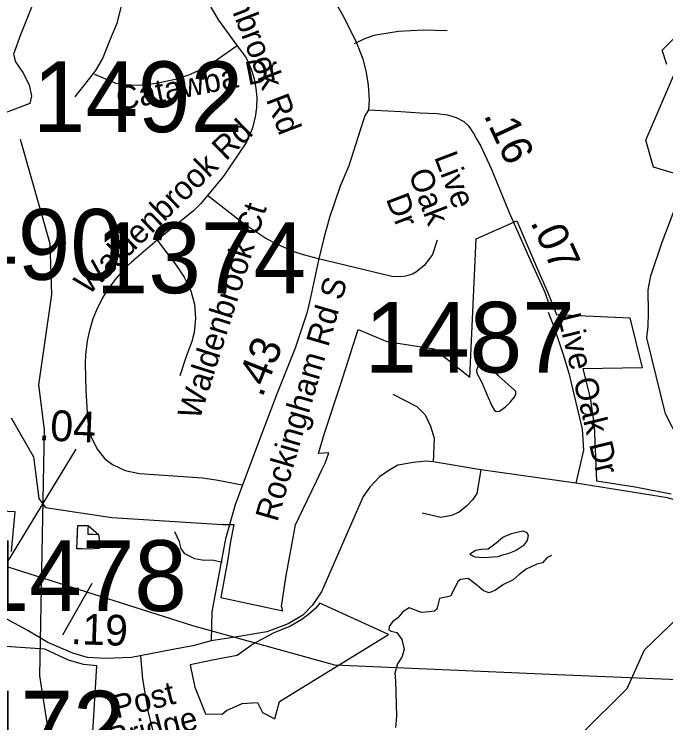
# Model space of a CAD drawing. Extents: x 1662474 to 1856135, y 779280 to 917889.
# Drawn here: x 1735258 to 1737912, y 817764 to 820649 of the extents above; entities that cross this region are included whole.
import ezdxf

# ---------------------------------------------------------------- set-up
doc = ezdxf.new("R2010")
doc.units = 0
for name, color, linetype in [('Cogo Default Point CELL', 7, 'Continuous'), ('Exist Boundary Political City Limit New', 7, 'Continuous'), ('Exist Boundary Political City Limit New Hole', 7, 'Continuous'), ('Exist Hydrographic Creek Single Shore', 7, 'Continuous'), ('Exist Hydrographic Misc Water Feature', 7, 'Continuous'), ('Exist Hydrographic Pond Under 1500 Sq Ft', 7, 'Continuous'), ('Exist Road Non-System Type 51', 7, 'Continuous'), ('Exist Road Non-System Type 51 Label', 7, 'Continuous'), ('Exist Road Secondary Mileage Tenths English Label', 7, 'Continuous'), ('Exist Road Secondary Type 51 Attributed', 7, 'Continuous'), ('Exist Road Secondary Type 51 Label', 7, 'Continuous'), ('Exist Utilities Electrical Transmission Line', 7, 'Continuous'), ('Map Preparation Boundary City Limit Buffer Line', 7, 'Continuous'), ('Prop DGN Element Guardrail', 7, 'Continuous')]:
    doc.layers.add(name, color=color, linetype=linetype)

msp = doc.modelspace()

# ---------------------------------------------------------------- linework, layer by layer
at = {"layer": 'Exist Boundary Political City Limit New'}
for points in [[(1737915.6, 820444.8), (1737896.8, 820502.2), (1737962.2, 820567.4)], [(1738049.1, 818752), (1737910.5, 819022.8), (1737834.9, 819331), (1737840.5, 819379.6), (1737841.6, 819433.6), (1737839.6, 819526.6), (1737850.8, 819583.7), (1737896.6, 819720.4), (1737997.5, 819985.3), (1737862, 820026.4), (1737831, 820135.9), (1737947.4, 820407.4)], [(1735245.1, 819006.1), (1735336, 818847.1), (1735358.5, 818677.1), (1735384.9, 818640.8), (1735655.2, 818599.9), (1736105.6, 818571.8), (1736153, 818571.2), (1736139.2, 818502.4), (1736126.9, 818421.8), (1736099.4, 818274.9), (1736352.2, 818220.5), (1736347, 818237.8), (1736364.5, 818355.5), (1736403.2, 818570.9), (1736433.1, 818632.6), (1736489, 818748.3), (1736511.2, 818794.4), (1736524.5, 818821.8), (1736539.2, 818863.3), (1736498, 818860.2), (1736521.8, 818943.9), (1736587.1, 819140.1), (1736659.2, 819365.4), (1736775.4, 819316), (1736968.6, 819287.2), (1737114.1, 819171.2), (1737139.5, 819734.6), (1737304.9, 819807.4), (1737385.9, 819621.1), (1737433, 819512.2), (1737467.2, 819425.9), (1737766.2, 819412.8), (1737815.8, 819209), (1737573.8, 819205.9), (1737604.4, 819087.4), (1737620.5, 818974.2), (1737630, 818749.4), (1737787.1, 818725.4), (1737933.5, 818696.2)], [(1735247, 818461.5), (1735262.1, 818622.6), (1735081.5, 818631.2)], [(1738046, 817674.9), (1738138.4, 818307.4), (1738180.8, 818423.3), (1738135.1, 818381.3), (1738071.8, 818298.6), (1737823.9, 818060.2), (1737752.9, 817902.8), (1737570.5, 817721)], [(1735560.4, 817433), (1735594.5, 817996.6), (1735540.2, 818001.2), (1735479.1, 818018.8), (1735382.8, 818064.1), (1735203.4, 818076.8)]]:
    msp.add_lwpolyline(points, dxfattribs=at)
at = {"layer": 'Exist Boundary Political City Limit New Hole'}
msp.add_lwpolyline([(1736487.1, 818231.6), (1736457.2, 818205.4), (1736429.8, 818185.2), (1736380.5, 818157), (1736315.1, 818131), (1736232.2, 818085.8), (1736165.8, 818037.7), (1736064.9, 818018.8), (1735974.2, 818000.2), (1735985.1, 817947.1), (1735992.9, 817909), (1736037.6, 817801.4), (1736104.9, 817799.7), (1736122.9, 817814.8), (1736186, 817843.1), (1736248.9, 817847.3), (1736269.8, 817806.8), (1736319.4, 817780.8), (1736338.9, 817850.5), (1736782.2, 818124.1), (1736503.2, 818251), (1736487.1, 818231.6)], dxfattribs=at)
at = {"layer": 'Exist Hydrographic Creek Single Shore'}
msp.add_lwpolyline([(1737446.2, 818445.3), (1737426.9, 818436.1), (1737410, 818415.4), (1737386.9, 818409.9), (1737343.4, 818389.6), (1737314.2, 818368.6), (1737290.6, 818346.1), (1737251, 818326.9), (1737219, 818303.6), (1737192.5, 818293.9), (1737170.1, 818301.8), (1737141, 818325.6), (1737106.9, 818351.9), (1737076.1, 818347.4), (1737066.2, 818340.8), (1737035.5, 818279.7), (1736989.6, 818270.8), (1736979.6, 818227.4), (1736969.4, 818218.2), (1736948.4, 818215.4), (1736917.1, 818213.8), (1736867.2, 818231.9), (1736841, 818215.9), (1736820.2, 818191.8), (1736799, 818174.7), (1736785.6, 818156.3), (1736783.8, 818143.2), (1736793.2, 818137.9), (1736817.1, 818132.4), (1736836.2, 818102.8), (1736846, 818062.9), (1736836.2, 818031.6), (1736818.5, 818004.4), (1736808.8, 817966), (1736811.1, 817934.8), (1736814.5, 817791.8), (1736810.6, 817745.8)], dxfattribs=at)
at = {"layer": 'Exist Hydrographic Misc Water Feature'}
for points in [[(1735582.6, 816470.9), (1735584.6, 816746.5), (1735511.6, 816961.3), (1735555.7, 817203.3), (1735532.7, 817413.9), (1735402.7, 817695.5), (1735362.8, 817955.7), (1735380.6, 818956.4), (1735357.6, 819140.7), (1735410.7, 819507.3), (1735404.6, 819714.2), (1735283, 820139.1)], [(1735603.5, 818473.4), (1735565.3, 818471.7), (1735533.4, 818472.1), (1735513.3, 818472.3), (1735513.7, 818504.2), (1735516.1, 818548.2), (1735516.3, 818568.2), (1735534.4, 818568.1), (1735558.4, 818567.9), (1735558, 818549.9), (1735558, 818531.9), (1735577.9, 818531.7), (1735601.8, 818531.4), (1735603.7, 818513.4), (1735601.4, 818495.4), (1735603.5, 818473.4)], [(1735603.5, 818473.4), (1735565.3, 818471.7), (1735533.4, 818472.1), (1735513.3, 818472.3), (1735513.7, 818504.2), (1735516.3, 818568.2), (1735534.4, 818568.1), (1735558.4, 818567.9), (1735601.8, 818531.4), (1735603.7, 818513.4), (1735603.5, 818473.4)]]:
    msp.add_lwpolyline(points, dxfattribs=at)
at = {"layer": 'Exist Hydrographic Pond Under 1500 Sq Ft'}
for points in [[(1735429.9, 820932.9), (1735284.1, 820565.7), (1735255, 820487), (1735263.7, 820455), (1735292.9, 820411.2), (1735319.1, 820361.7), (1735327.9, 820315.1), (1735322, 820285.9), (1735036.3, 820178.1), (1735010, 820189.8), (1734986.7, 820303.4), (1734896.3, 820449.1), (1734800.1, 820539.5), (1734709.7, 820583.2), (1734657.2, 820615.3), (1734645.6, 820650.2)], [(1737296.2, 819119), (1737231.6, 819175.1), (1737188.4, 819213.9), (1737170.3, 819223.3), (1737156.5, 819220.7), (1737145.3, 819210.4), (1737141, 819200.1), (1737142.7, 819188), (1737162.6, 819150.1), (1737176.4, 819116.5), (1737188.4, 819088.9), (1737204, 819054.4), (1737212.6, 819038.9), (1737221.2, 819031.1), (1737234.1, 819032.9), (1737259.2, 819050.1), (1737279.8, 819071.6), (1737295.4, 819090.6), (1737301.4, 819103.5), (1737301.4, 819113), (1737296.2, 819119)], [(1737228.3, 818439.7), (1737171.2, 818435.8), (1737134.9, 818438.4), (1737116.7, 818447.5), (1737115.4, 818452.6), (1737136.2, 818466.9), (1737159.6, 818470.8), (1737188.1, 818472.1), (1737220.5, 818496.7), (1737247.8, 818520.1), (1737284.1, 818534.3), (1737311.3, 818542.1), (1737330.8, 818546), (1737346.4, 818539.5), (1737351.6, 818526.6), (1737347.7, 818507.1), (1737330.8, 818485.1), (1737302.3, 818465.6), (1737268.5, 818452.6), (1737246.5, 818446.2), (1737228.3, 818439.7)]]:
    msp.add_lwpolyline(points, dxfattribs=at)
at = {"layer": 'Exist Road Non-System Type 51'}
for p, q in [((1737158.6, 818794.1), (1736964.9, 818827.2)), ((1737545.4, 818740.2), (1737158.6, 818794.1))]:
    msp.add_line(p, q, dxfattribs=at)
for points in [[(1735969.1, 821413.4), (1735970.9, 821250.2), (1735983, 820947.1), (1735986.4, 820911.1), (1735999.5, 820838.7), (1736020.9, 820765.9), (1736060.6, 820675.4), (1736089.9, 820625.2), (1736166.5, 820519.8)], [(1737021.4, 820582), (1736923.4, 820583.5), (1736822.6, 820578.2), (1736722.6, 820561.8), (1736685.1, 820548.1), (1736643.1, 820528.4)], [(1736166.5, 820519.8), (1736070.6, 820453.4), (1736002.4, 820415.6), (1735967.2, 820401.2), (1735913.1, 820383.6), (1735837.1, 820366.8), (1735764.9, 820359.4), (1735704.5, 820361.8), (1735673.6, 820367), (1735585.6, 820404)], [(1736166.5, 820519.8), (1736199.9, 820474.9), (1736209, 820458.1), (1736224.1, 820421.4), (1736235.2, 820385.4), (1736242.6, 820347.9), (1736245.8, 820309.2), (1736244.9, 820269.4), (1736239.6, 820230), (1736227.6, 820182.5), (1736204.5, 820128.4), (1736110, 819989.1), (1736045.8, 819910.6)], [(1736045.8, 819910.6), (1736016.6, 819876.8), (1735988, 819848.9), (1735840.2, 819728.7)], [(1736497.4, 819653.7), (1736436, 819669.9), (1736398.2, 819682.2), (1736330.2, 819711.1), (1736282.5, 819736.1), (1736192.8, 819795.9), (1736045.8, 819910.6)], [(1735840.2, 819728.7), (1735735, 819640), (1735707.1, 819613.5), (1735669.9, 819570.2), (1735636.6, 819525.4), (1735617.9, 819494.9), (1735592.8, 819443.7), (1735578.6, 819408.5), (1735562.5, 819356.2), (1735554.9, 819319.2), (1735547.6, 819262.6), (1735546.8, 819226.9), (1735549.4, 819116.9), (1735556.2, 819005.1), (1735560.6, 818969.4), (1735570.4, 818931.6), (1735595.6, 818878.1), (1735626.9, 818839.5), (1735658.4, 818815.6), (1735710.1, 818792), (1735768.1, 818779.1), (1736024.2, 818761), (1736080.6, 818753.4), (1736186.4, 818733.4)], [(1735840.2, 819728.7), (1735917.6, 819626.9), (1735949.6, 819578.9), (1735976.1, 819526.6), (1735991.9, 819468.6), (1735996.9, 819410.1), (1735991.4, 819353.9), (1735981.4, 819316.4), (1735956.8, 819251), (1735932.1, 819176.2)], [(1736980.9, 819728.7), (1736961.1, 819671.2), (1736950.6, 819655.5), (1736927.1, 819626.4), (1736896.9, 819600.6), (1736879.6, 819591.2), (1736851.5, 819582), (1736831.9, 819579.9), (1736795.9, 819581.8), (1736497.4, 819653.7)], [(1737432.7, 819435.5), (1737457, 819373.4), (1737494.5, 819264.2), (1737517.1, 819187.2), (1737571.9, 818959.9), (1737577.1, 818874.7), (1737545.4, 818740.2)], [(1736800.1, 819102.2), (1736897.6, 819052.6), (1736932.1, 819018.2), (1736954.1, 818971.8), (1736968.9, 818922.7), (1736964.9, 818827.2)], [(1736964.9, 818827.2), (1736935.8, 818829.8), (1736884.4, 818823.5), (1736820.5, 818812.8), (1736787.4, 818794.4), (1736745.8, 818766), (1736706.4, 818723.8), (1736678.8, 818686.2), (1736509.8, 818297.2), (1736471.6, 818242.4), (1736433.4, 818202.8), (1736374.4, 818166.8), (1736286.4, 818135), (1736165.4, 818114.9), (1736059.9, 818097.8)], [(1737158.6, 818794.1), (1737142.6, 818697.2), (1737125.5, 818673.1), (1737100.9, 818647.4), (1737070.1, 818621.7), (1737038.9, 818608), (1736995.6, 818600.7), (1736919.8, 818617.7)], [(1738249.6, 818457.9), (1738006.9, 818643.7), (1737974.4, 818663.4), (1737918.9, 818680.7), (1737545.4, 818740.2)], [(1736104.8, 818416.9), (1736071.1, 818424.6), (1736023.9, 818425.9), (1735993.4, 818432.1), (1735952.9, 818452.4), (1735937.9, 818474.4), (1735930.9, 818501.5), (1735912, 818541.2)], [(1735772, 818036.1), (1735779.9, 817941.4), (1735803.2, 817805.9), (1735825, 817720.9), (1735881.1, 817612.2), (1735989.9, 817422.2), (1736031.4, 817340.9), (1736044.1, 817273.9), (1736065.6, 817035.1), (1736080.1, 816997), (1736138.1, 816930.4)]]:
    msp.add_lwpolyline(points, dxfattribs=at)
at = {"layer": 'Exist Road Secondary Mileage Tenths English Label'}
msp.add_line((1735150.7, 818289.2), (1735510.2, 818877.7), dxfattribs=at)
at = {"layer": 'Exist Road Secondary Type 51 Attributed'}
for points in [[(1736594.9, 821695.7), (1736536.5, 821560.8), (1736502.9, 821480.2), (1736481.1, 821404.7), (1736461.2, 821321.5), (1736451.1, 821264.4), (1736424.3, 821093.3), (1736424.3, 821022.8), (1736429.3, 820979.2), (1736441.1, 820933.9), (1736471, 820862.7), (1736531.5, 820758.6), (1736595.3, 820646.2), (1736649, 820538.8), (1736678.1, 820466.8), (1736691.2, 820412.3), (1736699.9, 820360.1), (1736703.2, 820300.4), (1736701.3, 820259.6)], [(1735304.2, 821558.3), (1735388.6, 821494.4), (1735462.1, 821424.7), (1735541.5, 821329.5), (1735582.5, 821279), (1735620.8, 821213), (1735650.8, 821146.1), (1735668.4, 821086), (1735700.2, 820959), (1735708.3, 820897.5), (1735710.8, 820826.7), (1735704.7, 820755.6), (1735693.6, 820683.3), (1735675.9, 820611.1), (1735646, 820540.7), (1735618.5, 820471.1), (1735589.1, 820419.3), (1735504.3, 820312.7)], [(1736701.3, 820259.6), (1736686.1, 820234.7), (1736667.7, 820177.6), (1736620.4, 820031.8), (1736585.6, 819949.4), (1736541.6, 819821.2), (1736518.6, 819737), (1736497.6, 819647.1), (1736465, 819496), (1736457.4, 819465.4), (1736449.3, 819431.3), (1736402.1, 819289.8), (1736329.1, 819106.2), (1736265.9, 818941.9), (1736194.1, 818751), (1736158, 818651.6), (1736118.3, 818513.2), (1736063.1, 818216.7), (1736059.9, 818097.8)], [(1736701.3, 820259.6), (1736832.7, 820253.1), (1736911.6, 820248.1), (1736980.5, 820244.7), (1737022.4, 820239.7), (1737057.7, 820227.9), (1737089.6, 820212.8), (1737107.1, 820195.8), (1737119.7, 820178.6), (1737130.6, 820161.4), (1737141.5, 820141.5), (1737158.7, 820111.7), (1737200.4, 820021.5), (1737274.3, 819842), (1737358.2, 819652.4), (1737419.4, 819517.3), (1737437.1, 819465.6)], [(1736059.9, 818097.8), (1735986, 818077.5), (1735897.1, 818061.9), (1735735.4, 818030.6), (1735629.6, 818026.1), (1735555.8, 818030.6), (1735496, 818047.9), (1735395.4, 818090.9), (1735311.2, 818140.9), (1735176.7, 818213.3), (1735019.8, 818296.8)]]:
    msp.add_lwpolyline(points, dxfattribs=at)
at = {"layer": 'Exist Road Secondary Type 51 Label'}
msp.add_lwpolyline([(1735574.6, 818330.9), (1735454.6, 818121.1)], dxfattribs=at)
msp.add_lwpolyline([(1735574.6, 818330.9), (1735454.6, 818121.1)], dxfattribs=at)
at = {"layer": 'Exist Utilities Electrical Transmission Line'}
msp.add_lwpolyline([(1740410.3, 818536), (1739647.3, 818606.7), (1738818.7, 818695.7), (1738408.3, 818240), (1738124, 817932.3), (1737470.7, 817959.1), (1736563.3, 817999.5), (1735985.6, 818159.3), (1735318.6, 818370.5), (1734562, 818610.7), (1734385.1, 818673.4), (1733771.7, 818709.9), (1733130.2, 818752.5), (1733004.3, 818758.3)], dxfattribs=at)
at = {"layer": 'Map Preparation Boundary City Limit Buffer Line'}
for points in [[(1737915.6, 820444.8), (1737896.8, 820502.2), (1737962.2, 820567.4)], [(1738049.1, 818752), (1737910.5, 819022.8), (1737834.9, 819331), (1737840.5, 819379.6), (1737841.6, 819433.6), (1737839.6, 819526.6), (1737850.8, 819583.7), (1737896.6, 819720.4), (1737997.5, 819985.3), (1737862, 820026.4), (1737831, 820135.9), (1737947.4, 820407.4)], [(1735245.1, 819006.1), (1735336, 818847.1), (1735358.5, 818677.1), (1735384.9, 818640.8), (1735655.2, 818599.9), (1736105.6, 818571.8), (1736153, 818571.2), (1736139.2, 818502.4), (1736126.9, 818421.8), (1736099.4, 818274.9), (1736352.2, 818220.5), (1736347, 818237.8), (1736364.5, 818355.5), (1736403.2, 818570.9), (1736433.1, 818632.6), (1736489, 818748.3), (1736511.2, 818794.4), (1736524.5, 818821.8), (1736539.2, 818863.3), (1736498, 818860.2), (1736521.8, 818943.9), (1736587.1, 819140.1), (1736659.2, 819365.4), (1736775.4, 819316), (1736968.6, 819287.2), (1737114.1, 819171.2), (1737139.5, 819734.6), (1737304.9, 819807.4), (1737385.9, 819621.1), (1737433, 819512.2), (1737467.2, 819425.9), (1737766.2, 819412.8), (1737815.8, 819209), (1737573.8, 819205.9), (1737604.4, 819087.4), (1737620.5, 818974.2), (1737630, 818749.4), (1737787.1, 818725.4), (1737933.5, 818696.2)], [(1735247, 818461.5), (1735262.1, 818622.6), (1735081.5, 818631.2)], [(1738046, 817674.9), (1738138.4, 818307.4), (1738180.8, 818423.3), (1738135.1, 818381.3), (1738071.8, 818298.6), (1737823.9, 818060.2), (1737752.9, 817902.8), (1737570.5, 817721)], [(1736487.1, 818231.6), (1736457.2, 818205.4), (1736429.8, 818185.2), (1736380.5, 818157), (1736315.1, 818131), (1736232.2, 818085.8), (1736165.8, 818037.7), (1736064.9, 818018.8), (1735974.2, 818000.2), (1735985.1, 817947.1), (1735992.9, 817909), (1736037.6, 817801.4), (1736104.9, 817799.7), (1736122.9, 817814.8), (1736186, 817843.1), (1736248.9, 817847.3), (1736269.8, 817806.8), (1736319.4, 817780.8), (1736338.9, 817850.5), (1736782.2, 818124.1), (1736503.2, 818251), (1736487.1, 818231.6)], [(1735560.4, 817433), (1735594.5, 817996.6), (1735540.2, 818001.2), (1735479.1, 818018.8), (1735382.8, 818064.1), (1735203.4, 818076.8)]]:
    msp.add_lwpolyline(points, dxfattribs=at)

# ---------------------------------------------------------------- texts
at = {"layer": 'Cogo Default Point CELL'}
for s, p in [('1492', (1735333.5, 820168.8)), ('1490', (1734843.9, 819567.8)), ('1374', (1735589.9, 819513.3)), ('1487', (1736684.5, 819189.9)), ('1478', (1735104.4, 818219.6)), ('1472', (1734854.8, 817606.5))]:
    msp.add_text(s, height=288, dxfattribs=at).set_placement(p)
at = {"layer": 'Exist Road Non-System Type 51 Label'}
for s, rotation, p in [('Waldenbrook Rd', 290.9423, (1736002.1, 821034.2)), ('Catawba Dr', 11.1737, (1735683.5, 820255.7)), ('Waldenbrook Rd', 44.3358, (1735559.5, 819501.1)), ('Waldenbrook Ct', 72.4169, (1736012.2, 818993.5)), ('Live Oak Dr', 283.795, (1737470.7, 819419.9))]:
    msp.add_text(s, height=95, rotation=rotation, dxfattribs=at).set_placement(p)
at = {"layer": 'Exist Road Secondary Mileage Tenths English Label'}
for s, rotation, p in [('.43', 68.3184, (1736268, 819085.5)), ('.04', 357.5047, (1735356.2, 818914.9)), ('.19', 358.0346, (1735486.7, 818085.2))]:
    msp.add_text(s, height=125, rotation=rotation, dxfattribs=at).set_placement(p)
at = {"layer": 'Exist Road Secondary Type 51 Label'}
for s, rotation, p in [('Live ', 290.8151, (1736967.3, 820067.7)), ('Oak', 290.8151, (1736862.4, 820000.5)), (' Dr', 290.8151, (1736758.4, 819930.8)), ('Rockingham Rd S', 73.7733, (1736329.5, 818578.8)), ('Post ', 14.2168, (1735674.3, 817781.1)), ('Bridge', 14.2168, (1735656.6, 817650.8))]:
    msp.add_text(s, height=95, rotation=rotation, dxfattribs=at).set_placement(p)
at = {"layer": 'Prop DGN Element Guardrail'}
for s, rotation, p in [('.16', 294.8484, (1737168.9, 820238.3)), ('.07', 294.3759, (1737358.8, 819802.4))]:
    msp.add_text(s, height=125, rotation=rotation, dxfattribs=at).set_placement(p)

doc.saveas('drawing.dxf')
